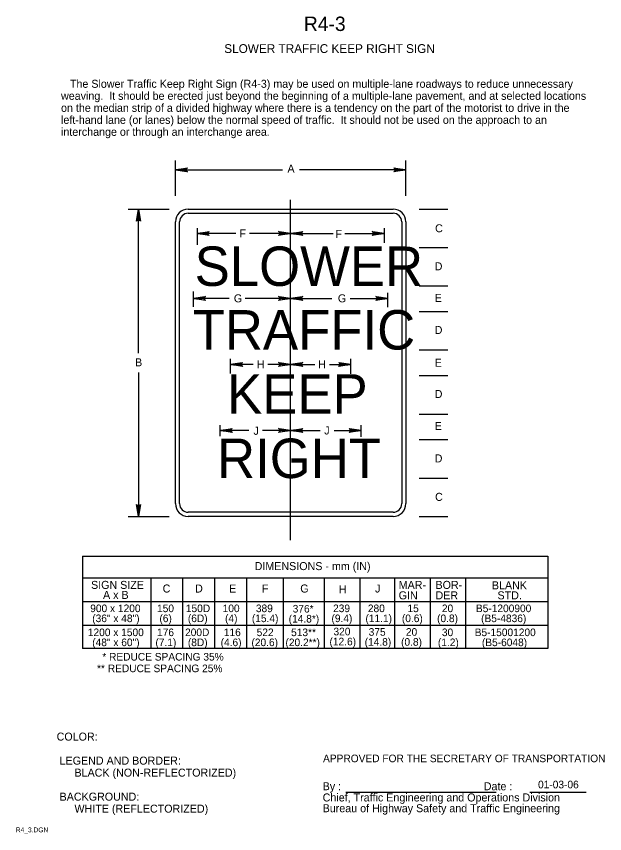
# Model space of a CAD drawing. Extents: x 0.013 to 0.196, y 0.004 to 0.259.
import ezdxf

# ---------------------------------------------------------------- set-up
doc = ezdxf.new("R2010")
doc.units = 0
for name, color, linetype in [('1', 7, 'Continuous'), ('2', 7, 'Continuous'), ('3', 7, 'Continuous'), ('4', 7, 'Continuous'), ('6', 7, 'Continuous')]:
    doc.layers.add(name, color=color, linetype=linetype)

# ---------------------------------------------------------------- blocks, each defined once
blk = doc.blocks.new('RARROW')
at = {"layer": '3'}
for p, q in [((-2.156, 0.285), (-2.2665, 0.384625)), ((-2.2665, 0.384625), (0, 0)), ((0, 0), (-2.2665, -0.379125)), ((-2.156, 0.285), (-2.075625, 0.12075)), ((0, 0), (-2.156, 0.285)), ((-2.14975, -0.2705), (0, 0)), ((-2.075625, 0.12075), (0, 0)), ((0, 0), (-2.074, -0.108)), ((-2.2665, -0.379125), (-2.14975, -0.2705)), ((-2.074, -0.108), (-2.14975, -0.2705))]:
    blk.add_line(p, q, dxfattribs=at)

msp = doc.modelspace()

# ---------------------------------------------------------------- linework, layer by layer
at = {"layer": '1'}
for p, q in [((0.06225, 0.20312), (0.06225, 0.21413)), ((0.13425, 0.20312), (0.13425, 0.21413)), ((0.06225, 0.21125), (0.09575, 0.21125)), ((0.13425, 0.21125), (0.101, 0.21125)), ((0.09825, 0.09563), (0.09825, 0.20187)), ((0.0475, 0.199), (0.06025, 0.199)), ((0.05075, 0.154), (0.05075, 0.199)), ((0.13837, 0.199), (0.14738, 0.199)), ((0.069, 0.193), (0.069, 0.18788)), ((0.1275, 0.193), (0.1275, 0.1885)), ((0.08113, 0.19138), (0.069, 0.19138)), ((0.09825, 0.19138), (0.08538, 0.19138)), ((0.09825, 0.19138), (0.1115, 0.19138)), ((0.11513, 0.19138), (0.1275, 0.19138)), ((0.13837, 0.187), (0.14738, 0.187)), ((0.13837, 0.175), (0.14738, 0.175)), ((0.06788, 0.1685), (0.06788, 0.17325)), ((0.079, 0.17112), (0.06788, 0.17112)), ((0.09825, 0.17112), (0.084, 0.17112)), ((0.09825, 0.17112), (0.11113, 0.17112)), ((0.11688, 0.17112), (0.12862, 0.17112)), ((0.12862, 0.16837), (0.12862, 0.17288)), ((0.13837, 0.167), (0.14738, 0.167)), ((0.13837, 0.155), (0.14738, 0.155)), ((0.0795, 0.14763), (0.0795, 0.15225)), ((0.117, 0.1475), (0.117, 0.15225)), ((0.0865, 0.1505), (0.0795, 0.1505)), ((0.09825, 0.1505), (0.09112, 0.1505)), ((0.09825, 0.1505), (0.10575, 0.1505)), ((0.11038, 0.1505), (0.117, 0.1505)), ((0.05075, 0.148), (0.05075, 0.103)), ((0.13837, 0.147), (0.14738, 0.147)), ((0.13837, 0.135), (0.14738, 0.135)), ((0.07625, 0.12812), (0.07625, 0.1315)), ((0.12025, 0.12788), (0.12025, 0.1315)), ((0.08513, 0.12987), (0.07625, 0.12987)), ((0.09825, 0.12987), (0.0895, 0.12987)), ((0.09825, 0.12987), (0.1075, 0.12987)), ((0.11188, 0.12987), (0.12025, 0.12987)), ((0.13837, 0.127), (0.14738, 0.127)), ((0.13837, 0.115), (0.14738, 0.115)), ((0.0475, 0.103), (0.06025, 0.103)), ((0.13837, 0.103), (0.14738, 0.103)), ((0.11544, 0.01695), (0.16242, 0.01695)), ((0.17295, 0.01695), (0.19056, 0.01695))]:
    msp.add_line(p, q, dxfattribs=at)
at = {"layer": '3'}
for p, q in [((0.06625, 0.199), (0.13025, 0.199)), ((0.06625, 0.1977), (0.13025, 0.1977)), ((0.06225, 0.107), (0.06225, 0.195)), ((0.06355, 0.107), (0.06355, 0.195)), ((0.13295, 0.195), (0.13295, 0.107)), ((0.13425, 0.195), (0.13425, 0.107)), ((0.13025, 0.1043), (0.06625, 0.1043)), ((0.13025, 0.103), (0.06625, 0.103)), ((0.03325, 0.09062), (0.17863, 0.09062)), ((0.03325, 0.09062), (0.03325, 0.06175)), ((0.17863, 0.09062), (0.17863, 0.06175)), ((0.17863, 0.08375), (0.03325, 0.08375)), ((0.05454, 0.08375), (0.05454, 0.06175)), ((0.0645, 0.08375), (0.0645, 0.06175)), ((0.0745, 0.08375), (0.0745, 0.06175)), ((0.0845, 0.08375), (0.0845, 0.06175)), ((0.09588, 0.08375), (0.09588, 0.06175)), ((0.10875, 0.08375), (0.10875, 0.06175)), ((0.11988, 0.08375), (0.11988, 0.06175)), ((0.13067, 0.08375), (0.13067, 0.06175)), ((0.14179, 0.08375), (0.14179, 0.06175)), ((0.15292, 0.08375), (0.15292, 0.06175)), ((0.17863, 0.07637), (0.03325, 0.07637)), ((0.17863, 0.069), (0.03325, 0.069)), ((0.17863, 0.06175), (0.03325, 0.06175))]:
    msp.add_line(p, q, dxfattribs=at)
for centre, radius, start, end in [((0.06625, 0.195), 0.004, 90, 180), ((0.06625, 0.195), 0.0027, 90, 180), ((0.13025, 0.195), 0.004, 0, 90), ((0.13025, 0.195), 0.0027, 0, 90), ((0.06625, 0.107), 0.004, 180, 270), ((0.06625, 0.107), 0.0027, 180, 270), ((0.13025, 0.107), 0.004, 270, 0), ((0.13025, 0.107), 0.0027, 270, 0)]:
    msp.add_arc(centre, radius, start, end, dxfattribs=at)

# ---------------------------------------------------------------- block references
at = {"layer": '3', "xscale": 0.0016545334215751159, "yscale": 0.0016366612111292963}
for p, rotation in [((0.06225, 0.21125), 180), ((0.05075, 0.199), 90), ((0.069, 0.19138), 180), ((0.09825, 0.19138), 180), ((0.06788, 0.17112), 180), ((0.09825, 0.17112), 180), ((0.0795, 0.1505), 180), ((0.09825, 0.1505), 180), ((0.07625, 0.12987), 180), ((0.09825, 0.12987), 180), ((0.05075, 0.103), -90.00000000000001)]:
    msp.add_blockref('RARROW', p, dxfattribs=dict(at, rotation=rotation))
for p in [(0.13425, 0.21125), (0.09825, 0.19138), (0.1275, 0.19138), (0.09825, 0.17112), (0.12862, 0.17112), (0.09825, 0.1505), (0.117, 0.1505), (0.09825, 0.12987), (0.12025, 0.12987)]:
    msp.add_blockref('RARROW', p, dxfattribs=at)

# ---------------------------------------------------------------- texts
at = {"layer": '1'}
for s, height, p in [('R4-3', 0.0045, (0.10238, 0.25462)), ('SLOWER TRAFFIC KEEP RIGHT SIGN', 0.0027503, (0.0775, 0.24775)), ('A', 0.0025, (0.09725, 0.21038)), ('C', 0.0025, (0.14338, 0.19175)), ('F', 0.0025, (0.08225, 0.19013)), ('F', 0.0025, (0.11225, 0.19)), ('D', 0.0025, (0.14325, 0.17988)), ('G', 0.0025, (0.0805, 0.16987)), ('G', 0.0025, (0.113, 0.16987)), ('E', 0.0025, (0.14325, 0.17)), ('D', 0.0025, (0.14325, 0.16)), ('B', 0.0025, (0.04963, 0.14988)), ('H', 0.0025, (0.08763, 0.14925)), ('H', 0.0025, (0.10687, 0.14925)), ('E', 0.0025, (0.14325, 0.14975)), ('D', 0.0025, (0.14325, 0.14)), ('J', 0.0025, (0.08663, 0.1285)), ('J', 0.0025, (0.10875, 0.12862)), ('E', 0.0025, (0.14325, 0.13)), ('D', 0.0025, (0.14325, 0.11988)), ('C', 0.0025, (0.14338, 0.10787)), ('COLOR:', 0.0025, (0.02513, 0.033)), ('APPROVED FOR THE SECRETARY OF TRANSPORTATION', 0.0023752, (0.10837, 0.02625)), (' LEGEND AND BORDER:', 0.0024998, (0.02513, 0.0255)), ('      BLACK (NON-REFLECTORIZED)', 0.0024998, (0.02513, 0.02175)), ('By :                                                Date :', 0.0024998, (0.10825, 0.0175)), (' BACKGROUND:', 0.0024998, (0.02513, 0.01425)), ('Chief, Traffic Engineering and Operations Division', 0.0024998, (0.10825, 0.014)), ('      WHITE (REFLECTORIZED)', 0.0024998, (0.02513, 0.0105)), ('Bureau of Highway Safety and Traffic Engineering', 0.0024998, (0.10825, 0.01063)), ('R4_3.DGN', 0.0015, (0.01238, 0.00438))]:
    msp.add_text(s, height=height, dxfattribs=at).set_placement(p)
at = {"layer": '2'}
for s, height, p in [('   The Slower Traffic Keep Right Sign (R4-3) may be used on multiple-lane roadways to reduce unnecessary', 0.00249975, (0.0265, 0.23688)), ('weaving.  It should be erected just beyond the beginning of a multiple-lane pavement, and at selected locations', 0.00249975, (0.0265, 0.23312)), ('on the median strip of a divided highway where there is a tendency on the part of the motorist to drive in the', 0.00249975, (0.0265, 0.22937)), ('left-hand lane (or lanes) below the normal speed of traffic.  It should not be used on the approach to an', 0.00249975, (0.0265, 0.22562)), ('interchange or through an interchange area.', 0.0024998, (0.0265, 0.22188))]:
    msp.add_text(s, height=height, dxfattribs=at).set_placement(p)
at = {"layer": '3'}
for s, height, p in [('DIMENSIONS - mm (IN)', 0.0024998, (0.087, 0.08625)), ('SIGN SIZE', 0.0025, (0.03588, 0.08038)), ('C', 0.0025, (0.05825, 0.07925)), ('D', 0.0025, (0.06838, 0.07925)), ('E', 0.0025, (0.079, 0.07925)), ('F', 0.0025, (0.08925, 0.07925)), ('G', 0.0025, (0.10125, 0.07925)), ('J', 0.0025, (0.12462, 0.07925)), ('MAR-', 0.0025, (0.132, 0.08038)), ('BOR-', 0.0025, (0.1435, 0.08038)), ('BLANK', 0.0025, (0.16112, 0.08025)), ('A x B', 0.0025, (0.03963, 0.07725)), ('H', 0.0025, (0.11325, 0.079)), ('GIN', 0.0025, (0.132, 0.07712)), ('DER', 0.0025, (0.1435, 0.07712)), ('STD.', 0.0025, (0.16287, 0.07712)), ('900 x 1200', 0.002375, (0.03563, 0.07312)), ('150', 0.002375, (0.0565, 0.07312)), ('150D', 0.002375, (0.0655, 0.07312)), ('100', 0.002375, (0.077, 0.07312)), ('389', 0.002375, (0.08738, 0.07312)), ('376*', 0.002375, (0.09888, 0.073)), ('239', 0.002375, (0.1115, 0.07312)), ('280', 0.002375, (0.12237, 0.07312)), ('15', 0.002375, (0.13475, 0.07312)), ('20', 0.002375, (0.1455, 0.07312)), ('B5-1200900', 0.002375, (0.15613, 0.07312)), ('(36" x 48")', 0.0023752, (0.03625, 0.07)), ('(6)', 0.002375, (0.05725, 0.07)), ('(6D)', 0.002375, (0.06613, 0.07)), ('(4)', 0.002375, (0.07775, 0.07)), ('(15.4)', 0.002375, (0.08613, 0.07)), ('(14.8*)', 0.002375, (0.09763, 0.06988)), ('(9.4)', 0.002375, (0.111, 0.07)), ('(11.1)', 0.002375, (0.12162, 0.07)), ('(0.6)', 0.002375, (0.133, 0.07)), ('(0.8)', 0.002375, (0.144, 0.07)), ('(B5-4836)', 0.002375, (0.15775, 0.07)), ('1200 x 1500', 0.0023752, (0.03488, 0.06563)), ('176', 0.002375, (0.0565, 0.06563)), ('200D', 0.002375, (0.06525, 0.06563)), ('116', 0.002375, (0.07737, 0.06563)), ('522', 0.002375, (0.08763, 0.06563)), ('513**', 0.002375, (0.09838, 0.06563)), ('320', 0.002375, (0.11163, 0.06588)), ('375', 0.002375, (0.12262, 0.06575)), ('20', 0.002375, (0.13425, 0.06575)), ('30', 0.002375, (0.1455, 0.06563)), ('B5-15001200', 0.0023752, (0.15575, 0.06563)), ('(48" x 60")', 0.0023752, (0.03625, 0.0625)), ('(7.1)', 0.002375, (0.056, 0.0625)), ('(8D)', 0.002375, (0.06613, 0.0625)), ('(4.6)', 0.002375, (0.07637, 0.0625)), ('(20.6)', 0.002375, (0.086, 0.0625)), ('(20.2**)', 0.002375, (0.09663, 0.0625)), ('(12.6)', 0.002375, (0.11038, 0.06275)), ('(14.8)', 0.002375, (0.12137, 0.06263)), ('(0.8)', 0.002375, (0.13275, 0.06263)), ('(1.2)', 0.002375, (0.14425, 0.0625)), ('(B5-6048)', 0.002375, (0.158, 0.0625)), ('* REDUCE SPACING 35%', 0.0023752, (0.03938, 0.058)), ('** REDUCE SPACING 25%', 0.0023752, (0.03775, 0.05437))]:
    msp.add_text(s, height=height, dxfattribs=at).set_placement(p)
at = {"layer": '4'}
msp.add_text('01-03-06', height=0.002375, dxfattribs=at).set_placement((0.17554, 0.0181))
at = {"layer": '6'}
for s, p in [('SLOWER', (0.06825, 0.175)), ('TRAFFIC', (0.06763, 0.15513)), ('KEEP', (0.07838, 0.13512)), ('RIGHT', (0.07525, 0.115))]:
    msp.add_text(s, height=0.012316, dxfattribs=at).set_placement(p)

doc.saveas('drawing.dxf')
